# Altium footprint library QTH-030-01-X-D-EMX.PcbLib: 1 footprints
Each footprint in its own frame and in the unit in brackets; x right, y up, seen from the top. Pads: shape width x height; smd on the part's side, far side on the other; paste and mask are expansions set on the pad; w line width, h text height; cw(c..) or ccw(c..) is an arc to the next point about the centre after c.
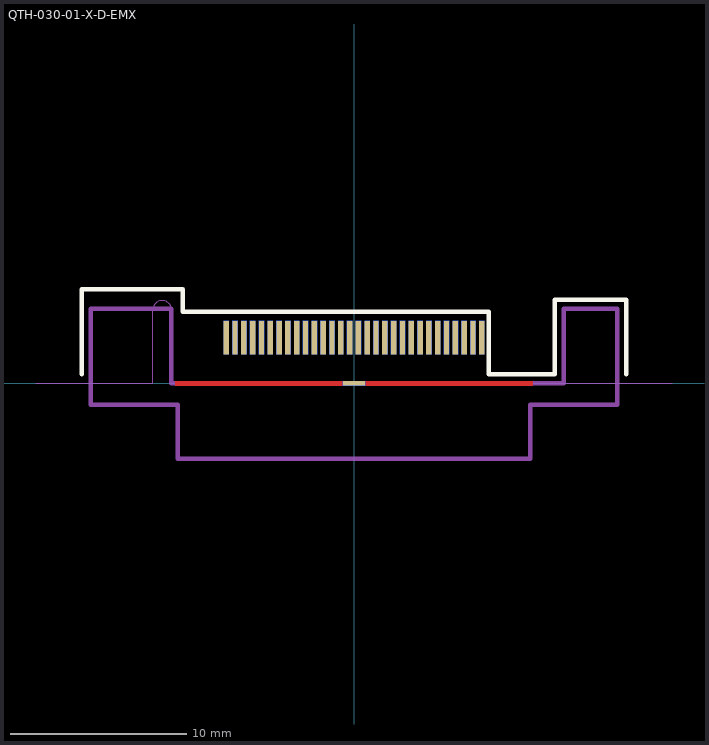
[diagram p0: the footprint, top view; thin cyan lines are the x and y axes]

## QTH-030-01-X-D-EMX [mil]
pads (62):
  rect 12x75 smd: 1(-285.65,102.5) 3(-265.95,102.5) 5(-246.25,102.5) 7(-226.55,102.5) 9(-206.85,102.5) 11(-187.15,102.5) 13(-167.45,102.5) 15(-147.75,102.5) 17(-128.05,102.5) 19(-108.35,102.5) 21(-88.65,102.5) 23(-68.95,102.5) 25(-49.25,102.5) 27(-29.55,102.5) 29(-9.85,102.5) 31(9.85,102.5) 33(29.55,102.5) 35(49.25,102.5) 37(68.95,102.5) 39(88.65,102.5) 41(108.35,102.5) 43(128.05,102.5) 45(147.75,102.5) 47(167.45,102.5) 49(187.15,102.5) 51(206.85,102.5) 53(226.55,102.5) 55(246.25,102.5) 57(265.95,102.5) 59(285.65,102.5)
  rect 12x75 smd far side: 2(-285.65,102.5) 4(-265.95,102.5) 6(-246.25,102.5) 8(-226.55,102.5) 10(-206.85,102.5) 12(-187.15,102.5) 14(-167.45,102.5) 16(-147.75,102.5) 18(-128.05,102.5) 20(-108.35,102.5) 22(-88.65,102.5) 24(-68.95,102.5) 26(-49.25,102.5) 28(-29.55,102.5) 30(-9.85,102.5) 32(9.85,102.5) 34(29.55,102.5) 36(49.25,102.5) 38(68.95,102.5) 40(88.65,102.5) 42(108.35,102.5) 44(128.05,102.5) 46(147.75,102.5) 48(167.45,102.5) 50(187.15,102.5) 52(206.85,102.5) 54(226.55,102.5) 56(246.25,102.5) 58(265.95,102.5) 60(285.65,102.5)
  rect 50x10 smd mask+2: 61(0,0)
  rect 50x10 smd far side: 62(0,0)
Top Layer:
  region: -400,5 400,5 400,-5 -400,-5
Bottom Layer:
  region: -400,5 400,5 400,-5 -400,-5
Top Overlay:
  lines w10: -608.75,20 -608.75,210 -382.5,210 -382.5,160 301.65,160 301.65,20 448.75,20 448.75,187 608.75,187 608.75,20
Bottom Overlay:
  lines w10: -608.75,20 -608.75,210 -382.5,210 -382.5,160 301.65,160 301.65,20 448.75,20 448.75,187 608.75,187 608.75,20
Top Paste:
  drawing of 30 lines, arcs and shapes, not listed
Bottom Paste:
  drawing of 30 lines, arcs and shapes, not listed
Top Solder:
  drawing of 31 lines, arcs and shapes, not listed
Bottom Solder:
  drawing of 31 lines, arcs and shapes, not listed
Mechanical 1:
  lines w10: -588.75,-48 -393.75,-48 -393.75,-168 393.75,-168 393.75,-48 588.75,-48 588.75,167 468.75,167 468.75,0 -408.75,0 -408.75,167 -588.75,167 -588.75,-48
  text "J1" at -17.56,-227.99 h30
Mechanical 16:
  lines w0.1: -711.25,0 -450.35,0 -450.35,163.5 cw(c-428.85,163.5) -407.35,163.5 -407.35,0 711.25,0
